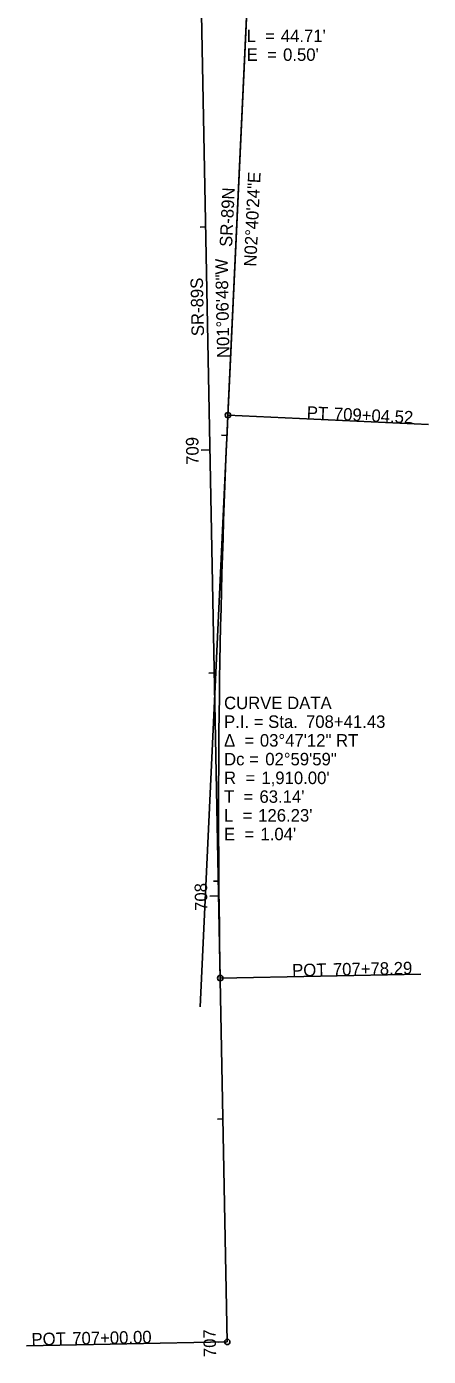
# Model space of a CAD drawing. Extents: x 2047151 to 2048731, y 456453 to 457874.
# Drawn here: x 2047598.5 to 2047688.6, y 456453.3 to 456751.4 of the extents above; entities that cross this region are included whole.
import ezdxf

# ---------------------------------------------------------------- set-up
doc = ezdxf.new("R2010")
doc.units = 0
for name, color, linetype in [('GE_P_Alignment', 7, 'Continuous'), ('GE_P_Alignment_100_Bearings', 7, 'Continuous'), ('GE_P_Alignment_100_Cardinal_Points', 7, 'Continuous'), ('GE_P_Alignment_100_Distances', 7, 'Continuous'), ('GE_P_Alignment_100_Stations', 7, 'Continuous'), ('GE_P_Alignment_500_Bearings', 7, 'Continuous'), ('GE_P_Alignment_500_Cardinal_Points', 7, 'Continuous'), ('GE_P_Alignment_500_Curve_Data', 7, 'Continuous'), ('GE_P_Alignment_500_Distances', 7, 'Continuous'), ('GE_P_Alignment_500_Stations', 7, 'Continuous')]:
    doc.layers.add(name, color=color, linetype=linetype)

msp = doc.modelspace()

# ---------------------------------------------------------------- linework, layer by layer
at = {"layer": 'GE_P_Alignment'}
for p, q in [((2047643.48, 456456.55), (2047633.52, 456968.93)), ((2047643.48, 456456.55), (2047634.45, 456921.29)), ((2047637.42, 456531.68), (2047648.82, 456775.95)), ((2047643.61, 456664.31), (2047647.78, 456753.6))]:
    msp.add_line(p, q, dxfattribs=at)
msp.add_arc((2049551.53, 456575.23), 1910, 177.3267, 181.11347, dxfattribs=at)
msp.add_arc((2049551.53, 456575.23), 1910, 177.3267, 181.11347, dxfattribs=at)
at = {"layer": 'GE_P_Alignment_100_Cardinal_Points'}
msp.add_line((2047643.48, 456456.55), (2047598.49, 456455.68), dxfattribs=at)
msp.add_circle((2047643.48, 456456.55), 0.6, dxfattribs=at)
at = {"layer": 'GE_P_Alignment_100_Stations'}
for p, q in [((2047638.62, 456706.51), (2047637.42, 456706.48)), ((2047639.59, 456656.52), (2047637.59, 456656.48)), ((2047640.56, 456606.53), (2047639.36, 456606.5)), ((2047641.54, 456556.53), (2047639.54, 456556.5)), ((2047642.51, 456506.54), (2047641.31, 456506.52)), ((2047643.48, 456456.55), (2047641.48, 456456.51))]:
    msp.add_line(p, q, dxfattribs=at)
at = {"layer": 'GE_P_Alignment_500_Cardinal_Points'}
for p, q in [((2047643.61, 456664.31), (2047688.56, 456662.21)), ((2047641.89, 456538.11), (2047686.89, 456538.99))]:
    msp.add_line(p, q, dxfattribs=at)
for centre in [(2047643.61, 456664.31), (2047641.89, 456538.11)]:
    msp.add_circle(centre, 0.6, dxfattribs=at)
at = {"layer": 'GE_P_Alignment_500_Stations'}
for p, q in [((2047643.41, 456659.79), (2047642.21, 456659.84)), ((2047641.6, 456559.82), (2047640.4, 456559.81))]:
    msp.add_line(p, q, dxfattribs=at)

# ---------------------------------------------------------------- texts
at = {"layer": 'GE_P_Alignment_100_Bearings'}
msp.add_text('N01°06\'48"W', height=2.8, rotation=91.1135, dxfattribs=at).set_placement((2047643.99, 456677.15))
at = {"layer": 'GE_P_Alignment_100_Cardinal_Points'}
for s, p in [('POT', (2047599.61, 456455.75)), ('707+00.00', (2047608.74, 456455.93))]:
    msp.add_text(s, height=2.8, rotation=1.1135, dxfattribs=at).set_placement(p)
at = {"layer": 'GE_P_Alignment_100_Distances'}
msp.add_text('SR-89S', height=2.8, rotation=91.1135, dxfattribs=at).set_placement((2047638.27, 456682.05))
at = {"layer": 'GE_P_Alignment_100_Stations'}
for s, p in [('709', (2047637.11, 456653.21)), ('708', (2047639.05, 456553.21)), ('707', (2047641, 456453.17))]:
    msp.add_text(s, height=2.8, rotation=91.1135, dxfattribs=at).set_placement(p)
at = {"layer": 'GE_P_Alignment_500_Bearings'}
msp.add_text('N02°40\'24"E', height=2.8, rotation=87.3267, dxfattribs=at).set_placement((2047649.97, 456697.57))
at = {"layer": 'GE_P_Alignment_500_Cardinal_Points'}
for s, rotation, p in [('PT', 357.3267, (2047661.24, 456663.54)), ('709+04.52', 357.3267, (2047667.32, 456663.25)), ('POT', 1.1135, (2047658.04, 456538.47)), ('707+78.29', 1.1135, (2047667.17, 456538.65))]:
    msp.add_text(s, height=2.8, rotation=rotation, dxfattribs=at).set_placement(p)
at = {"layer": 'GE_P_Alignment_500_Curve_Data'}
for s, p in [('L  = ', (2047647.82, 456747.95)), ("44.71'", (2047655.47, 456747.95)), ('E  = ', (2047647.82, 456743.75)), ("0.50'", (2047655.98, 456743.75)), ('CURVE DATA', (2047642.75, 456598.41)), ('P.I. = Sta. ', (2047642.75, 456594.21)), ('708+41.43', (2047661.12, 456594.21)), ('Δ  = ', (2047642.75, 456590.01)), ('03°47\'12" RT', (2047650.78, 456590.01)), ('Dc = ', (2047642.75, 456585.81)), ('02°59\'59"', (2047651.99, 456585.81)), ('R  = ', (2047642.75, 456581.61)), ("1,910.00'", (2047651.12, 456581.61)), ('T  = ', (2047642.75, 456577.41)), ("63.14'", (2047650.69, 456577.41)), ('L  = ', (2047642.75, 456573.21)), ("126.23'", (2047650.4, 456573.21)), ('E  = ', (2047642.75, 456569.01)), ("1.04'", (2047650.91, 456569.01))]:
    msp.add_text(s, height=2.8, dxfattribs=at).set_placement(p)
at = {"layer": 'GE_P_Alignment_500_Distances'}
msp.add_text('SR-89N', height=2.8, rotation=87.3267, dxfattribs=at).set_placement((2047644.55, 456701.99))

doc.saveas('drawing.dxf')
